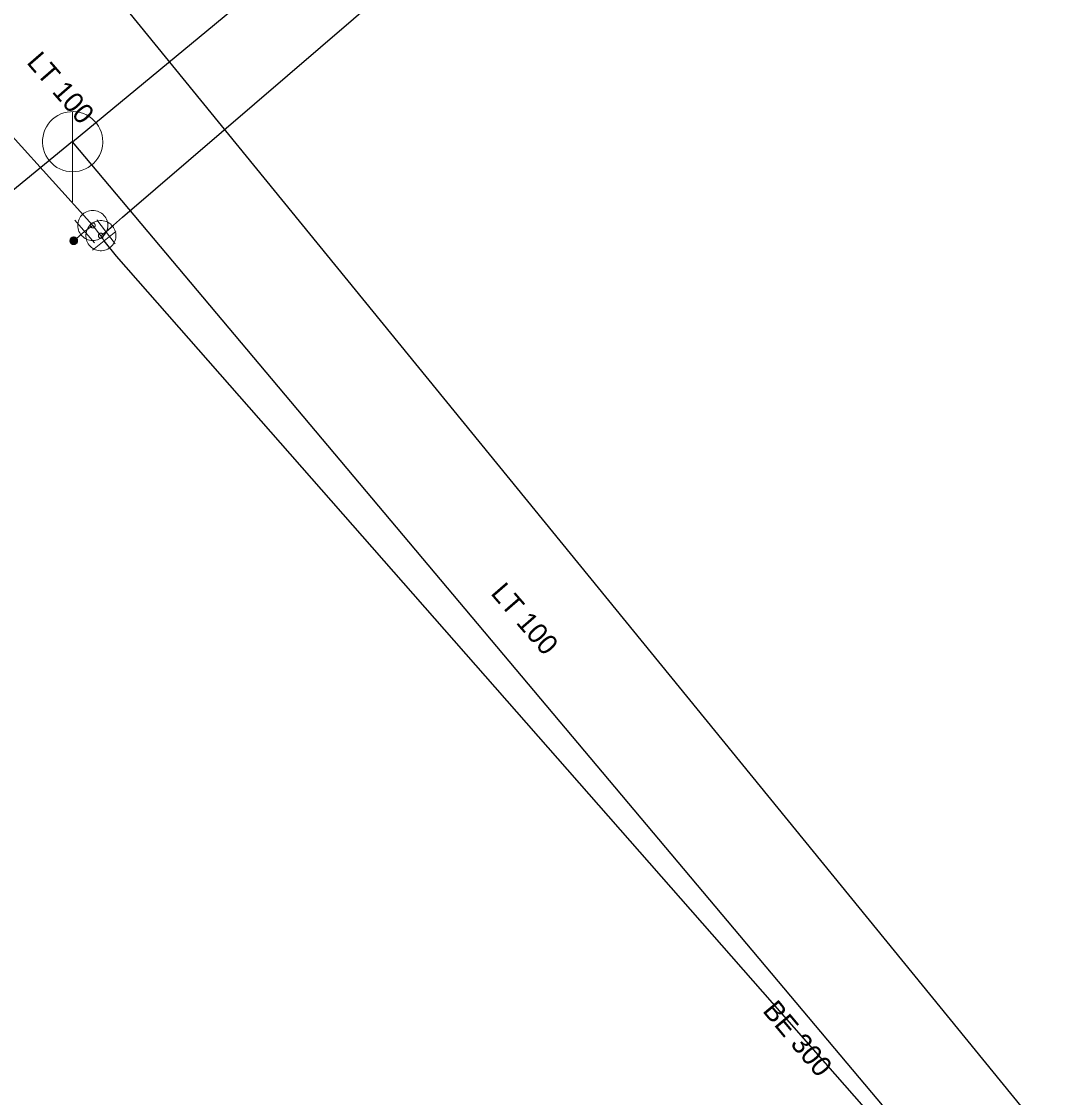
# Model space of a CAD drawing. Extents: x -688296 to -687852, y -973332 to -972816.
# Drawn here: x -688207.25 to -688173.21, y -973168.31 to -973132.54 of the extents above; entities that cross this region are included whole.
import ezdxf
from ezdxf.enums import TextEntityAlignment as Align

# ---------------------------------------------------------------- set-up
doc = ezdxf.new("R2010")
doc.units = 0
doc.header["$LTSCALE"] = 0.27
for name, color, linetype, lineweight in [('1', 7, 'Continuous', 25), ('14', 7, 'Continuous', 13), ('17', 7, 'Continuous', 25), ('22', 7, 'Continuous', 13), ('34', 7, 'Continuous', 13), ('47', 7, 'Continuous', 13), ('9', 7, 'Continuous', 13)]:
    doc.layers.add(name, color=color, linetype=linetype, lineweight=lineweight)

msp = doc.modelspace()

# ---------------------------------------------------------------- linework, layer by layer
at = {"layer": '14', "lineweight": 25}
for p, q in [((-688205.548, -973136.536), (-688173.864, -973110.353)), ((-688205.548, -973136.535), (-688243.846, -973167.688)), ((-688153.927, -973197.923), (-688205.548, -973136.536))]:
    msp.add_line(p, q, dxfattribs=at)
at = {"layer": '14'}
msp.add_line((-688205.149, -973139.52), (-688205.51, -973139.829), dxfattribs=at)
for points in [[(-688204.609, -973139.66), (-688204.879, -973139.32), (-688205.149, -973139.52)], [(-688204.5, -973139.829), (-688204.609, -973139.66), (-688204.44, -973139.53)]]:
    msp.add_lwpolyline(points, dxfattribs=at)
at = {"layer": '17'}
for points in [[(-688123.609, -972815.609), (-688135.91, -972839.761), (-688146.524, -972867.704), (-688149.164, -972878.87), (-688150.368, -972974.473), (-688134.778, -973051.136), (-688125.903, -973068.701), (-688203.651, -973132.27), (-688148.612, -973199.748), (-688078.631, -973291.807), (-688049.631, -973331.642)], [(-688204.44, -973139.53), (-688204.19, -973139.309), (-688203.89, -973139.05), (-688177.64, -973116.5), (-688162.42, -973104.039), (-688153.219, -973097.199), (-688149.52, -973093.53), (-688143.109, -973089.09)], [(-688207.94, -973135.84), (-688207.62, -973136.28), (-688207.559, -973136.35), (-688204.879, -973139.32)], [(-688177.473, -973170.632), (-688204.09, -973140.34), (-688204.5, -973139.829)]]:
    msp.add_lwpolyline(points, dxfattribs=at)
at = {"layer": '22'}
msp.add_line((-688205.548, -973138.536), (-688205.547, -973135.536), dxfattribs=at)
msp.add_lwpolyline([(-688204.548, -973136.536), (-688204.553, -973136.427), (-688204.571, -973136.319), (-688204.601, -973136.213), (-688204.641, -973136.112), (-688204.693, -973136.015), (-688204.755, -973135.925), (-688204.827, -973135.842), (-688204.907, -973135.768), (-688204.995, -973135.702), (-688205.089, -973135.647), (-688205.189, -973135.602), (-688205.294, -973135.569), (-688205.401, -973135.547), (-688205.51, -973135.537), (-688205.62, -973135.539), (-688205.728, -973135.553), (-688205.835, -973135.578), (-688205.938, -973135.615), (-688206.036, -973135.664), (-688206.128, -973135.722), (-688206.214, -973135.791), (-688206.291, -973135.868), (-688206.36, -973135.954), (-688206.419, -973136.046), (-688206.467, -973136.144), (-688206.504, -973136.247), (-688206.53, -973136.354), (-688206.544, -973136.462), (-688206.547, -973136.572), (-688206.537, -973136.681), (-688206.516, -973136.788), (-688206.482, -973136.892), (-688206.438, -973136.992), (-688206.383, -973137.087), (-688206.317, -973137.175), (-688206.243, -973137.255), (-688206.16, -973137.327), (-688206.07, -973137.389), (-688205.974, -973137.441), (-688205.872, -973137.482), (-688205.767, -973137.512), (-688205.659, -973137.53), (-688205.549, -973137.536), (-688205.44, -973137.53), (-688205.332, -973137.512), (-688205.227, -973137.483), (-688205.125, -973137.442), (-688205.028, -973137.39), (-688204.938, -973137.328), (-688204.855, -973137.257), (-688204.78, -973137.177), (-688204.715, -973137.089), (-688204.659, -973136.995), (-688204.615, -973136.895), (-688204.581, -973136.791), (-688204.559, -973136.683), (-688204.549, -973136.574)], close=True, dxfattribs=at)
at = {"layer": '34'}
for p, q in [((-688204.822, -973139.898), (-688205.474, -973139.14)), ((-688204.744, -973139.133), (-688204.136, -973139.927)), ((-688204.889, -973140.142), (-688204.11, -973139.516))]:
    msp.add_line(p, q, dxfattribs=at)
at = {"layer": '47'}
for points in [[(-688204.544, -973139.691), (-688204.507, -973139.654), (-688204.474, -973139.613), (-688204.446, -973139.569), (-688204.422, -973139.523), (-688204.403, -973139.473), (-688204.39, -973139.422), (-688204.382, -973139.371), (-688204.379, -973139.319), (-688204.382, -973139.267), (-688204.39, -973139.215), (-688204.403, -973139.164), (-688204.423, -973139.116), (-688204.446, -973139.069), (-688204.475, -973139.025), (-688204.507, -973138.985), (-688204.544, -973138.948), (-688204.585, -973138.915), (-688204.63, -973138.886), (-688204.675, -973138.863), (-688204.725, -973138.844), (-688204.776, -973138.831), (-688204.827, -973138.822), (-688204.88, -973138.82), (-688204.932, -973138.822), (-688204.983, -973138.831), (-688205.034, -973138.844), (-688205.083, -973138.863), (-688205.129, -973138.887), (-688205.173, -973138.916), (-688205.213, -973138.948), (-688205.25, -973138.985), (-688205.283, -973139.026), (-688205.312, -973139.07), (-688205.335, -973139.116), (-688205.354, -973139.166), (-688205.368, -973139.216), (-688205.376, -973139.268), (-688205.379, -973139.32), (-688205.376, -973139.373), (-688205.367, -973139.424), (-688205.354, -973139.475), (-688205.336, -973139.523), (-688205.311, -973139.57), (-688205.282, -973139.614), (-688205.25, -973139.654), (-688205.213, -973139.691), (-688205.172, -973139.724), (-688205.129, -973139.753), (-688205.082, -973139.776), (-688205.032, -973139.795), (-688204.982, -973139.809), (-688204.931, -973139.817), (-688204.879, -973139.819), (-688204.826, -973139.816), (-688204.774, -973139.808), (-688204.723, -973139.795), (-688204.675, -973139.776), (-688204.628, -973139.752), (-688204.584, -973139.723)], [(-688204.88, -973139.24), (-688204.922, -973139.27), (-688204.961, -973139.305), (-688204.996, -973139.344), (-688205.027, -973139.386), (-688205.054, -973139.432), (-688205.075, -973139.48), (-688205.09, -973139.529), (-688205.101, -973139.581), (-688205.107, -973139.632), (-688205.108, -973139.685), (-688205.102, -973139.737), (-688205.091, -973139.788), (-688205.076, -973139.838), (-688205.054, -973139.886), (-688205.028, -973139.931), (-688204.998, -973139.973), (-688204.963, -973140.012), (-688204.923, -973140.048), (-688204.882, -973140.078), (-688204.836, -973140.105), (-688204.788, -973140.126), (-688204.738, -973140.142), (-688204.687, -973140.153), (-688204.635, -973140.159), (-688204.583, -973140.159), (-688204.531, -973140.153), (-688204.479, -973140.143), (-688204.43, -973140.127), (-688204.382, -973140.105), (-688204.337, -973140.079), (-688204.295, -973140.049), (-688204.256, -973140.014), (-688204.22, -973139.975), (-688204.19, -973139.933), (-688204.163, -973139.887), (-688204.142, -973139.84), (-688204.125, -973139.79), (-688204.114, -973139.739), (-688204.109, -973139.686), (-688204.109, -973139.634), (-688204.115, -973139.582), (-688204.125, -973139.531), (-688204.141, -973139.481), (-688204.163, -973139.433), (-688204.189, -973139.388), (-688204.219, -973139.346), (-688204.254, -973139.307), (-688204.293, -973139.272), (-688204.335, -973139.241), (-688204.381, -973139.214), (-688204.428, -973139.193), (-688204.478, -973139.177), (-688204.529, -973139.166), (-688204.581, -973139.161), (-688204.634, -973139.16), (-688204.686, -973139.166), (-688204.736, -973139.176), (-688204.787, -973139.192), (-688204.835, -973139.214)], [(-688204.824, -973139.38), (-688204.817, -973139.374), (-688204.812, -973139.368), (-688204.808, -973139.361), (-688204.804, -973139.353), (-688204.8, -973139.345), (-688204.799, -973139.336), (-688204.797, -973139.328), (-688204.796, -973139.319), (-688204.797, -973139.311), (-688204.798, -973139.302), (-688204.801, -973139.294), (-688204.804, -973139.286), (-688204.808, -973139.279), (-688204.812, -973139.271), (-688204.818, -973139.265), (-688204.824, -973139.258), (-688204.83, -973139.253), (-688204.837, -973139.249), (-688204.845, -973139.245), (-688204.853, -973139.241), (-688204.862, -973139.24), (-688204.87, -973139.238), (-688204.879, -973139.237), (-688204.888, -973139.238), (-688204.896, -973139.239), (-688204.904, -973139.242), (-688204.912, -973139.245), (-688204.919, -973139.249), (-688204.927, -973139.253), (-688204.933, -973139.259), (-688204.94, -973139.265), (-688204.945, -973139.271), (-688204.949, -973139.278), (-688204.953, -973139.286), (-688204.957, -973139.294), (-688204.959, -973139.302), (-688204.96, -973139.311), (-688204.961, -973139.32), (-688204.96, -973139.329), (-688204.959, -973139.337), (-688204.956, -973139.345), (-688204.953, -973139.353), (-688204.949, -973139.36), (-688204.945, -973139.368), (-688204.939, -973139.374), (-688204.933, -973139.381), (-688204.927, -973139.386), (-688204.92, -973139.39), (-688204.912, -973139.394), (-688204.904, -973139.398), (-688204.896, -973139.4), (-688204.887, -973139.401), (-688204.878, -973139.402), (-688204.87, -973139.401), (-688204.861, -973139.4), (-688204.853, -973139.397), (-688204.845, -973139.394), (-688204.838, -973139.39), (-688204.83, -973139.386)], [(-688204.653, -973139.591), (-688204.661, -973139.596), (-688204.666, -973139.602), (-688204.672, -973139.608), (-688204.677, -973139.614), (-688204.681, -973139.622), (-688204.685, -973139.63), (-688204.688, -973139.638), (-688204.69, -973139.646), (-688204.69, -973139.655), (-688204.69, -973139.664), (-688204.689, -973139.673), (-688204.688, -973139.681), (-688204.685, -973139.689), (-688204.682, -973139.696), (-688204.677, -973139.704), (-688204.672, -973139.712), (-688204.666, -973139.717), (-688204.66, -973139.723), (-688204.654, -973139.728), (-688204.646, -973139.732), (-688204.638, -973139.736), (-688204.63, -973139.739), (-688204.622, -973139.741), (-688204.612, -973139.742), (-688204.604, -973139.741), (-688204.595, -973139.74), (-688204.587, -973139.739), (-688204.579, -973139.736), (-688204.572, -973139.733), (-688204.564, -973139.728), (-688204.556, -973139.723), (-688204.551, -973139.717), (-688204.545, -973139.711), (-688204.54, -973139.705), (-688204.536, -973139.697), (-688204.532, -973139.69), (-688204.529, -973139.681), (-688204.527, -973139.673), (-688204.526, -973139.663), (-688204.527, -973139.655), (-688204.528, -973139.646), (-688204.529, -973139.638), (-688204.532, -973139.63), (-688204.535, -973139.623), (-688204.54, -973139.615), (-688204.545, -973139.607), (-688204.551, -973139.602), (-688204.557, -973139.596), (-688204.563, -973139.591), (-688204.571, -973139.587), (-688204.578, -973139.583), (-688204.587, -973139.58), (-688204.595, -973139.578), (-688204.604, -973139.578), (-688204.613, -973139.578), (-688204.622, -973139.579), (-688204.63, -973139.58), (-688204.638, -973139.583), (-688204.645, -973139.586)]]:
    msp.add_lwpolyline(points, close=True, dxfattribs=at)
at = {"layer": '9'}
for points in [[(-688205.636, -973139.829), (-688205.636, -973139.842), (-688205.634, -973139.855), (-688205.631, -973139.868), (-688205.626, -973139.88), (-688205.62, -973139.892), (-688205.613, -973139.903), (-688205.605, -973139.913), (-688205.595, -973139.923), (-688205.585, -973139.931), (-688205.574, -973139.938), (-688205.562, -973139.944), (-688205.55, -973139.949), (-688205.537, -973139.952), (-688205.524, -973139.954), (-688205.511, -973139.956), (-688205.498, -973139.955), (-688205.485, -973139.953), (-688205.472, -973139.95), (-688205.46, -973139.945), (-688205.448, -973139.939), (-688205.437, -973139.932), (-688205.427, -973139.924), (-688205.417, -973139.914), (-688205.409, -973139.904), (-688205.402, -973139.893), (-688205.396, -973139.881), (-688205.391, -973139.869), (-688205.388, -973139.856), (-688205.386, -973139.843), (-688205.384, -973139.83), (-688205.385, -973139.817), (-688205.387, -973139.804), (-688205.39, -973139.791), (-688205.395, -973139.779), (-688205.401, -973139.767), (-688205.408, -973139.756), (-688205.416, -973139.746), (-688205.426, -973139.736), (-688205.436, -973139.728), (-688205.447, -973139.721), (-688205.459, -973139.715), (-688205.471, -973139.71), (-688205.484, -973139.707), (-688205.497, -973139.705), (-688205.51, -973139.704), (-688205.523, -973139.704), (-688205.536, -973139.706), (-688205.549, -973139.709), (-688205.561, -973139.714), (-688205.573, -973139.72), (-688205.584, -973139.727), (-688205.594, -973139.735), (-688205.604, -973139.745), (-688205.612, -973139.755), (-688205.619, -973139.766), (-688205.625, -973139.778), (-688205.63, -973139.79), (-688205.633, -973139.803), (-688205.635, -973139.816)], [(-688205.616, -973139.829), (-688205.617, -973139.84), (-688205.615, -973139.851), (-688205.612, -973139.862), (-688205.608, -973139.872), (-688205.603, -973139.882), (-688205.597, -973139.891), (-688205.59, -973139.9), (-688205.582, -973139.908), (-688205.573, -973139.915), (-688205.564, -973139.921), (-688205.554, -973139.926), (-688205.544, -973139.93), (-688205.533, -973139.933), (-688205.522, -973139.936), (-688205.511, -973139.936), (-688205.5, -973139.936), (-688205.489, -973139.934), (-688205.478, -973139.931), (-688205.468, -973139.927), (-688205.458, -973139.922), (-688205.449, -973139.916), (-688205.44, -973139.909), (-688205.432, -973139.901), (-688205.425, -973139.892), (-688205.419, -973139.883), (-688205.414, -973139.873), (-688205.41, -973139.863), (-688205.407, -973139.852), (-688205.405, -973139.841), (-688205.404, -973139.83), (-688205.404, -973139.819), (-688205.406, -973139.808), (-688205.409, -973139.797), (-688205.413, -973139.787), (-688205.418, -973139.777), (-688205.424, -973139.768), (-688205.431, -973139.759), (-688205.439, -973139.751), (-688205.448, -973139.744), (-688205.457, -973139.738), (-688205.467, -973139.733), (-688205.477, -973139.729), (-688205.488, -973139.726), (-688205.499, -973139.724), (-688205.51, -973139.724), (-688205.521, -973139.723), (-688205.532, -973139.725), (-688205.543, -973139.728), (-688205.553, -973139.732), (-688205.563, -973139.737), (-688205.572, -973139.743), (-688205.581, -973139.75), (-688205.589, -973139.758), (-688205.596, -973139.767), (-688205.602, -973139.776), (-688205.607, -973139.786), (-688205.611, -973139.796), (-688205.614, -973139.807), (-688205.616, -973139.818)], [(-688205.597, -973139.829), (-688205.597, -973139.838), (-688205.596, -973139.847), (-688205.593, -973139.856), (-688205.59, -973139.864), (-688205.586, -973139.872), (-688205.581, -973139.88), (-688205.575, -973139.887), (-688205.569, -973139.893), (-688205.562, -973139.899), (-688205.554, -973139.904), (-688205.546, -973139.908), (-688205.538, -973139.911), (-688205.529, -973139.914), (-688205.52, -973139.915), (-688205.511, -973139.917), (-688205.502, -973139.916), (-688205.493, -973139.915), (-688205.484, -973139.912), (-688205.476, -973139.909), (-688205.468, -973139.905), (-688205.46, -973139.9), (-688205.453, -973139.894), (-688205.447, -973139.888), (-688205.441, -973139.881), (-688205.436, -973139.873), (-688205.432, -973139.865), (-688205.429, -973139.857), (-688205.426, -973139.848), (-688205.425, -973139.839), (-688205.423, -973139.83), (-688205.424, -973139.821), (-688205.425, -973139.812), (-688205.428, -973139.803), (-688205.431, -973139.795), (-688205.435, -973139.787), (-688205.44, -973139.779), (-688205.446, -973139.772), (-688205.452, -973139.766), (-688205.459, -973139.76), (-688205.467, -973139.755), (-688205.475, -973139.751), (-688205.483, -973139.748), (-688205.492, -973139.745), (-688205.501, -973139.744), (-688205.51, -973139.743), (-688205.519, -973139.743), (-688205.528, -973139.744), (-688205.537, -973139.747), (-688205.545, -973139.75), (-688205.553, -973139.754), (-688205.561, -973139.759), (-688205.568, -973139.765), (-688205.574, -973139.771), (-688205.58, -973139.778), (-688205.585, -973139.786), (-688205.589, -973139.794), (-688205.592, -973139.802), (-688205.595, -973139.811), (-688205.596, -973139.82)], [(-688205.577, -973139.829), (-688205.577, -973139.836), (-688205.576, -973139.843), (-688205.575, -973139.85), (-688205.572, -973139.856), (-688205.569, -973139.862), (-688205.565, -973139.868), (-688205.561, -973139.874), (-688205.556, -973139.879), (-688205.55, -973139.883), (-688205.544, -973139.887), (-688205.538, -973139.89), (-688205.532, -973139.893), (-688205.525, -973139.894), (-688205.518, -973139.897), (-688205.511, -973139.897), (-688205.504, -973139.897), (-688205.497, -973139.895), (-688205.49, -973139.894), (-688205.484, -973139.891), (-688205.477, -973139.888), (-688205.472, -973139.884), (-688205.466, -973139.88), (-688205.461, -973139.875), (-688205.457, -973139.869), (-688205.453, -973139.863), (-688205.45, -973139.857), (-688205.447, -973139.851), (-688205.445, -973139.844), (-688205.444, -973139.837), (-688205.443, -973139.83), (-688205.443, -973139.823), (-688205.444, -973139.816), (-688205.446, -973139.809), (-688205.449, -973139.803), (-688205.452, -973139.796), (-688205.456, -973139.791), (-688205.46, -973139.785), (-688205.465, -973139.78), (-688205.471, -973139.776), (-688205.476, -973139.772), (-688205.483, -973139.769), (-688205.489, -973139.766), (-688205.496, -973139.764), (-688205.503, -973139.763), (-688205.51, -973139.763), (-688205.517, -973139.763), (-688205.524, -973139.763), (-688205.531, -973139.765), (-688205.537, -973139.768), (-688205.543, -973139.771), (-688205.549, -973139.775), (-688205.555, -973139.779), (-688205.56, -973139.784), (-688205.564, -973139.79), (-688205.568, -973139.795), (-688205.571, -973139.802), (-688205.574, -973139.808), (-688205.575, -973139.815), (-688205.577, -973139.822)], [(-688205.557, -973139.829), (-688205.557, -973139.834), (-688205.557, -973139.839), (-688205.556, -973139.844), (-688205.554, -973139.848), (-688205.552, -973139.853), (-688205.549, -973139.857), (-688205.546, -973139.86), (-688205.542, -973139.864), (-688205.539, -973139.867), (-688205.535, -973139.87), (-688205.53, -973139.872), (-688205.526, -973139.874), (-688205.521, -973139.875), (-688205.516, -973139.877), (-688205.511, -973139.877), (-688205.506, -973139.877), (-688205.501, -973139.876), (-688205.496, -973139.875), (-688205.492, -973139.873), (-688205.487, -973139.871), (-688205.483, -973139.868), (-688205.479, -973139.865), (-688205.476, -973139.861), (-688205.473, -973139.858), (-688205.47, -973139.854), (-688205.468, -973139.849), (-688205.466, -973139.845), (-688205.465, -973139.84), (-688205.464, -973139.835), (-688205.463, -973139.83), (-688205.463, -973139.825), (-688205.464, -973139.82), (-688205.465, -973139.815), (-688205.467, -973139.811), (-688205.469, -973139.806), (-688205.472, -973139.802), (-688205.475, -973139.798), (-688205.478, -973139.795), (-688205.482, -973139.792), (-688205.486, -973139.789), (-688205.491, -973139.787), (-688205.495, -973139.785), (-688205.5, -973139.784), (-688205.505, -973139.783), (-688205.51, -973139.783), (-688205.515, -973139.783), (-688205.52, -973139.784), (-688205.525, -973139.784), (-688205.529, -973139.786), (-688205.534, -973139.788), (-688205.538, -973139.791), (-688205.541, -973139.794), (-688205.545, -973139.797), (-688205.548, -973139.801), (-688205.551, -973139.805), (-688205.553, -973139.81), (-688205.555, -973139.814), (-688205.556, -973139.819), (-688205.557, -973139.824)], [(-688205.537, -973139.829), (-688205.537, -973139.832), (-688205.538, -973139.835), (-688205.537, -973139.837), (-688205.536, -973139.84), (-688205.535, -973139.843), (-688205.533, -973139.845), (-688205.531, -973139.847), (-688205.529, -973139.849), (-688205.527, -973139.851), (-688205.525, -973139.853), (-688205.522, -973139.855), (-688205.519, -973139.856), (-688205.517, -973139.856), (-688205.514, -973139.857), (-688205.511, -973139.857), (-688205.508, -973139.857), (-688205.505, -973139.857), (-688205.502, -973139.856), (-688205.5, -973139.855), (-688205.497, -973139.854), (-688205.495, -973139.852), (-688205.492, -973139.85), (-688205.49, -973139.848), (-688205.489, -973139.846), (-688205.487, -973139.844), (-688205.486, -973139.841), (-688205.484, -973139.838), (-688205.484, -973139.836), (-688205.483, -973139.833), (-688205.482, -973139.83), (-688205.483, -973139.827), (-688205.483, -973139.824), (-688205.484, -973139.821), (-688205.485, -973139.819), (-688205.486, -973139.816), (-688205.488, -973139.814), (-688205.489, -973139.811), (-688205.491, -973139.809), (-688205.494, -973139.808), (-688205.496, -973139.806), (-688205.499, -973139.805), (-688205.501, -973139.804), (-688205.504, -973139.803), (-688205.507, -973139.803), (-688205.51, -973139.802), (-688205.513, -973139.803), (-688205.516, -973139.802), (-688205.518, -973139.804), (-688205.521, -973139.804), (-688205.524, -973139.805), (-688205.526, -973139.807), (-688205.528, -973139.808), (-688205.53, -973139.81), (-688205.532, -973139.813), (-688205.534, -973139.815), (-688205.535, -973139.818), (-688205.536, -973139.82), (-688205.537, -973139.823), (-688205.537, -973139.826)], [(-688205.518, -973139.829), (-688205.518, -973139.831), (-688205.518, -973139.831), (-688205.517, -973139.831), (-688205.517, -973139.833), (-688205.518, -973139.834), (-688205.516, -973139.834), (-688205.516, -973139.834), (-688205.516, -973139.836), (-688205.516, -973139.836), (-688205.515, -973139.837), (-688205.513, -973139.837), (-688205.513, -973139.837), (-688205.513, -973139.838), (-688205.511, -973139.838), (-688205.511, -973139.838), (-688205.51, -973139.838), (-688205.509, -973139.838), (-688205.509, -973139.837), (-688205.508, -973139.837), (-688205.506, -973139.837), (-688205.506, -973139.836), (-688205.506, -973139.836), (-688205.505, -973139.835), (-688205.505, -973139.835), (-688205.503, -973139.834), (-688205.503, -973139.833), (-688205.502, -973139.832), (-688205.502, -973139.832), (-688205.502, -973139.831), (-688205.502, -973139.83), (-688205.502, -973139.829), (-688205.502, -973139.828), (-688205.502, -973139.828), (-688205.503, -973139.827), (-688205.503, -973139.826), (-688205.504, -973139.825), (-688205.504, -973139.825), (-688205.505, -973139.824), (-688205.505, -973139.824), (-688205.506, -973139.823), (-688205.507, -973139.823), (-688205.508, -973139.822), (-688205.508, -973139.822), (-688205.509, -973139.822), (-688205.51, -973139.822), (-688205.511, -973139.822), (-688205.512, -973139.822), (-688205.512, -973139.822), (-688205.513, -973139.823), (-688205.514, -973139.822), (-688205.515, -973139.824), (-688205.515, -973139.824), (-688205.516, -973139.824), (-688205.516, -973139.824), (-688205.517, -973139.826), (-688205.517, -973139.827), (-688205.517, -973139.828), (-688205.518, -973139.828), (-688205.518, -973139.829)]]:
    msp.add_lwpolyline(points, close=True, dxfattribs=at)

# ---------------------------------------------------------------- texts
at = {"layer": '1'}
for s, rotation, p in [('LT 100', 311, (-688206.1912, -973134.96)), ('LT 100', 311, (-688206.1912, -973134.96)), ('LT 100', 311, (-688206.1912, -973134.96)), ('LT 100', 311, (-688206.1912, -973134.96)), ('LT 100', 311, (-688206.1912, -973134.96)), ('LT 100', 311, (-688190.7652, -973152.608)), ('LT 100', 311, (-688190.7652, -973152.608)), ('LT 100', 311, (-688190.7652, -973152.608)), ('LT 100', 311, (-688190.7652, -973152.608)), ('LT 100', 311, (-688190.7652, -973152.608)), ('BE 300', 310, (-688181.6969, -973166.5555)), ('BE 300', 310, (-688181.6969, -973166.5555)), ('BE 300', 310, (-688181.6969, -973166.5555)), ('BE 300', 310, (-688181.6969, -973166.5555)), ('BE 300', 310, (-688181.6969, -973166.5555))]:
    msp.add_text(s, height=0.6667, rotation=rotation, dxfattribs=at).set_placement(p, align=Align.CENTER)

doc.saveas('drawing.dxf')
